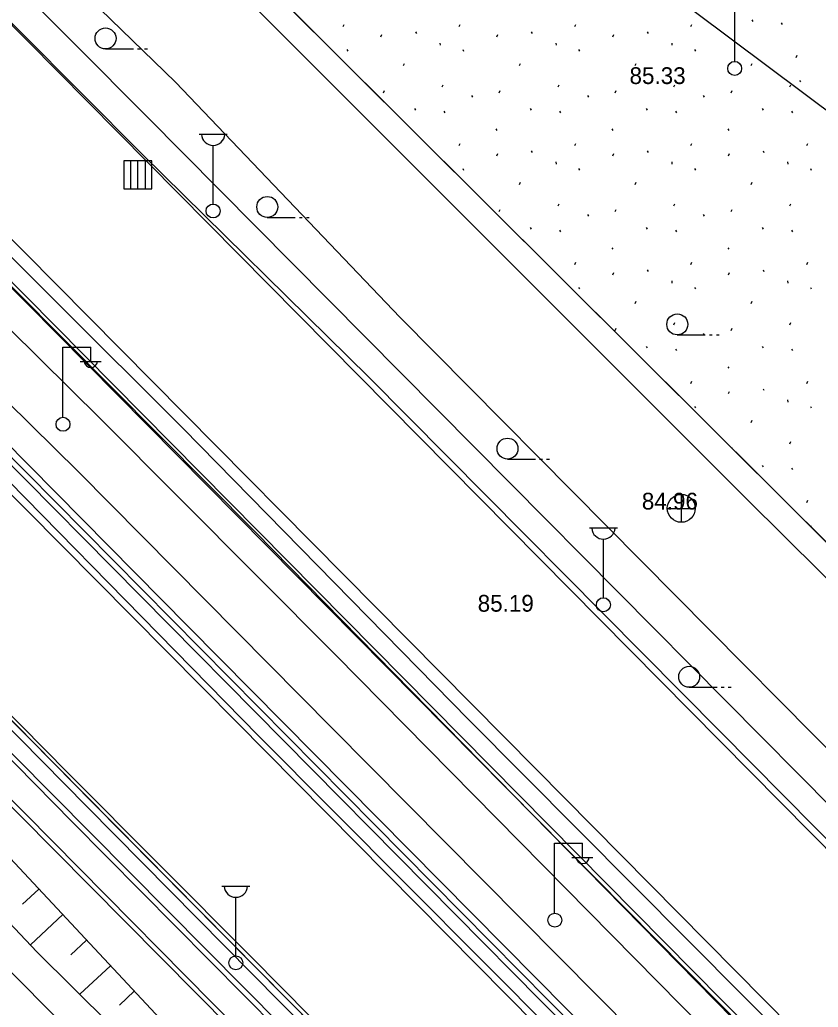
# Model space of a CAD drawing. Extents: x 412225 to 413380, y 4456471 to 4457189.
# Drawn here: x 412408.2 to 412465.4, y 4456938.5 to 4457009.2 of the extents above; entities that cross this region are included whole.
import ezdxf

# ---------------------------------------------------------------- set-up
doc = ezdxf.new("R2010")
doc.units = 0
for name, color, linetype in [('0_HALİHAZIR', 7, 'Continuous'), ('0_KADASTRO', 7, 'Continuous'), ('KALDIRIM', 7, 'Continuous'), ('Level 27', 7, 'Continuous'), ('Level 41', 7, 'Continuous'), ('Level 57', 7, 'Continuous'), ('Level 62', 7, 'Continuous'), ('Level 8', 7, 'Continuous')]:
    doc.layers.add(name, color=color, linetype=linetype)

msp = doc.modelspace()

# ---------------------------------------------------------------- linework, layer by layer
at = {"layer": '0_HALİHAZIR'}
for p, q in [((412459.38, 4457006.195), (412459.38, 4457010.388)), ((412414.357, 4457007.091), (412416.357, 4457007.091)), ((412416.657, 4457007.091), (412416.857, 4457007.091)), ((412417.157, 4457007.091), (412417.357, 4457007.091)), ((412421.055, 4457000.992), (412423.055, 4457000.992)), ((412422.055, 4456995.992), (412422.055, 4457000.185)), ((412417.675, 4456999.085), (412415.675, 4456999.085)), ((412415.675, 4456999.085), (412415.675, 4456997.085)), ((412417.675, 4456999.085), (412415.675, 4456999.085)), ((412415.675, 4456999.085), (412415.675, 4456997.085)), ((412416.18, 4456997.085), (412416.18, 4456999.085)), ((412416.675, 4456997.085), (412416.675, 4456999.085)), ((412417.223, 4456997.085), (412417.223, 4456999.085)), ((412417.675, 4456997.085), (412417.675, 4456999.085)), ((412417.675, 4456997.085), (412417.675, 4456999.085)), ((412415.675, 4456997.085), (412417.675, 4456997.085)), ((412415.675, 4456997.085), (412417.675, 4456997.085)), ((412425.932, 4456995.029), (412427.932, 4456995.029)), ((412428.232, 4456995.029), (412428.432, 4456995.029)), ((412428.732, 4456995.029), (412428.932, 4456995.029)), ((412455.275, 4456986.628), (412457.275, 4456986.628)), ((412457.575, 4456986.628), (412457.775, 4456986.628)), ((412458.075, 4456986.628), (412458.275, 4456986.628)), ((412411.305, 4456980.753), (412411.305, 4456985.753)), ((412411.305, 4456985.753), (412413.305, 4456985.753)), ((412413.305, 4456984.753), (412413.305, 4456985.753)), ((412412.545, 4456984.713), (412414.045, 4456984.713)), ((412443.122, 4456977.739), (412445.122, 4456977.739)), ((412445.422, 4456977.739), (412445.622, 4456977.739)), ((412445.922, 4456977.739), (412446.122, 4456977.739)), ((412455.572, 4456973.209), (412455.572, 4456975.209)), ((412454.552, 4456974.199), (412456.552, 4456974.199)), ((412448.984, 4456972.816), (412450.984, 4456972.816)), ((412449.984, 4456967.816), (412449.984, 4456972.009)), ((412456.122, 4456961.415), (412458.122, 4456961.415)), ((412458.422, 4456961.415), (412458.622, 4456961.415)), ((412458.922, 4456961.415), (412459.122, 4456961.415)), ((412446.497, 4456945.269), (412446.497, 4456950.269)), ((412446.497, 4456950.269), (412448.497, 4456950.269)), ((412448.497, 4456949.269), (412448.497, 4456950.269)), ((412447.737, 4456949.229), (412449.237, 4456949.229)), ((412422.685, 4456947.192), (412424.685, 4456947.192)), ((412409.586, 4456946.968), (412408.424, 4456945.882)), ((412423.685, 4456942.192), (412423.685, 4456946.385)), ((412411.293, 4456945.142), (412408.978, 4456942.978)), ((412413, 4456943.315), (412411.87, 4456942.259)), ((412414.707, 4456941.489), (412412.517, 4456939.441)), ((412416.414, 4456939.662), (412415.354, 4456938.671))]:
    msp.add_line(p, q, dxfattribs=at)
for points in [[(412301.706, 4457121.318), (412311.102, 4457113.16), (412330.158, 4457093.729), (412349.865, 4457074.031), (412372.694, 4457050.81), (412390.772, 4457032.428), (412419.372, 4457004.721)], [(412644.931, 4456753.555), (412630.555, 4456767.782), (412604.684, 4456793.709), (412582.154, 4456816.287), (412559.135, 4456839.628), (412534.75, 4456864.124), (412499.888, 4456899.345), (412487.433, 4456911.736), (412459.99, 4456939.333), (412440.337, 4456959.115), (412419.902, 4456979.921), (412392.691, 4457007.039), (412362.588, 4457037.58), (412334.209, 4457066.321), (412297.701, 4457103.437), (412284.18, 4457117.149)], [(412417.329, 4457002.236), (412381.395, 4457038.35), (412347.738, 4457072.166), (412303.554, 4457116.902)], [(412284.17, 4457116.265), (412296.803, 4457102.771), (412316.426, 4457082.291), (412338.061, 4457060.18), (412363.233, 4457034.899), (412383.867, 4457014.022), (412425.083, 4456972.499), (412446.131, 4456951.075), (412463.226, 4456933.647), (412501.75, 4456894.857), (412523.558, 4456872.918), (412554.446, 4456842.344)], [(412284.13, 4457112.788), (412289.83, 4457106.958), (412301.261, 4457094.649), (412314.468, 4457080.886), (412326.161, 4457068.858), (412338.147, 4457056.814), (412352.735, 4457042.191), (412364.851, 4457029.813), (412379.023, 4457015.687), (412394.281, 4457000.11), (412414.019, 4456980.608)], [(412284.053, 4457106.223), (412285.021, 4457105.263), (412297.191, 4457092.981), (412313.147, 4457076.941), (412329.843, 4457060.337), (412349.945, 4457039.93), (412369.246, 4457020.5), (412382.389, 4457007.084), (412402.176, 4456986.924), (412412.412, 4456976.824)], [(412283.977, 4457099.685), (412295.712, 4457088.125), (412305.906, 4457077.537), (412321.323, 4457062.165), (412336.439, 4457046.989), (412355.577, 4457027.567), (412370.703, 4457012.276), (412385.426, 4456997.416), (412408.728, 4456974.086)], [(412283.985, 4457100.322), (412303.353, 4457080.961), (412332.911, 4457051.149), (412362.488, 4457021.336), (412400.253, 4456983.455), (412425.306, 4456957.949), (412451.956, 4456931.175), (412483.613, 4456899.459), (412507.045, 4456875.463), (412533.953, 4456848.693), (412570.746, 4456810.938), (412594.382, 4456786.967), (412618.72, 4456762.275), (412633.267, 4456747.178), (412636.335, 4456744.215)], [(412340.966, 4457076.102), (412361.717, 4457055.451), (412377.534, 4457039.414), (412399.513, 4457017.111), (412417.007, 4456999.535), (412433.199, 4456983.611)], [(412361.686, 4456992.138), (412361.531, 4456995.933), (412361.158, 4456998.952), (412360.693, 4457001.526), (412360.272, 4457003.327), (412359.32, 4457005.483), (412358.676, 4457006.822), (412358.336, 4457007.638), (412358.163, 4457008.228), (412358.124, 4457008.638), (412358.202, 4457008.918), (412358.315, 4457009.019), (412358.874, 4457008.994), (412365.521, 4457001.843), (412376.984, 4456990.177), (412386.707, 4456980.556), (412399.955, 4456967.14), (412411.666, 4456955.297), (412424.812, 4456942.094), (412439.594, 4456927.156)], [(412513.116, 4456909.938), (412497.081, 4456925.639), (412469.945, 4456953.037), (412435.441, 4456987.862), (412419.372, 4457004.721)], [(412359.87, 4457004.239), (412376.982, 4456987.314), (412402.386, 4456961.963), (412429.729, 4456934.421), (412459.529, 4456904.105), (412465.296, 4456898.03)], [(412417.321, 4457002.244), (412443.331, 4456975.989), (412466.46, 4456952.659), (412490.035, 4456928.962), (412506.529, 4456912.027), (412510.582, 4456907.986)], [(412364.261, 4456996.871), (412370.245, 4456990.594), (412389.047, 4456971.622), (412405.68, 4456954.805), (412425.867, 4456934.44)], [(412645.421, 4456754.062), (412629.127, 4456770.178), (412599.147, 4456800.409), (412567.615, 4456832.31), (412536.489, 4456863.396), (412502.72, 4456897.599), (412471.675, 4456928.735), (412445.148, 4456955.565), (412406.259, 4456994.837)], [(412637.165, 4456746.318), (412618.159, 4456765.78), (412589.798, 4456794.375), (412560.702, 4456823.748), (412525.834, 4456858.92), (412495.532, 4456889.87), (412469.975, 4456915.531), (412420.275, 4456965.756), (412393.731, 4456992.619)], [(412446.303, 4456903.127), (412444.442, 4456907.882), (412437.794, 4456916.266), (412419.952, 4456935.877), (412400.449, 4456956.745), (412375.57, 4456982.136), (412370.301, 4456987.22), (412368.113, 4456988.47), (412366.809, 4456988.895), (412364.507, 4456988.91)], [(412364.559, 4456988.91), (412369.327, 4456983.178), (412377.302, 4456975.126), (412390.738, 4456962.288), (412409.437, 4456942.493), (412422.613, 4456929.438), (412434.169, 4456915.9), (412443.007, 4456906.151), (412446.303, 4456903.127)], [(412433.199, 4456983.611), (412458.357, 4456958.224), (412478.594, 4456937.778), (412494.707, 4456921.709), (412506.6, 4456909.868), (412508.244, 4456908.725), (412509.715, 4456908.155), (412510.968, 4456907.91), (412512.709, 4456907.952), (412514.827, 4456908.164), (412517.02, 4456908.788), (412521.642, 4456910.812), (412528.714, 4456914.991), (412542.04, 4456923.109), (412563.128, 4456935.466), (412569.855, 4456939.641), (412584.556, 4456948.006), (412584.762, 4456948.165)], [(412414.019, 4456980.608), (412430.818, 4456963.728), (412462.102, 4456931.987), (412481.52, 4456912.466), (412499.923, 4456893.817), (412530.253, 4456863.229), (412548.59, 4456844.546), (412567.492, 4456825.478), (412597.357, 4456795.212), (412619.629, 4456772.724)], [(412412.412, 4456976.824), (412430.58, 4456958.484), (412471.136, 4456917.576), (412494.611, 4456893.791), (412529.094, 4456859.09), (412552.718, 4456835.192), (412591.392, 4456796.015), (412615.481, 4456771.779), (412632.916, 4456754.119)], [(412635.095, 4456744.706), (412621.293, 4456758.968), (412594.514, 4456786.189), (412564.28, 4456816.959), (412527.989, 4456853.886), (412497.963, 4456883.985), (412468.818, 4456913.357), (412423.738, 4456958.933), (412408.728, 4456974.086)]]:
    msp.add_lwpolyline(points, dxfattribs=at)
for centre, radius in [((412414.357, 4457007.841), 0.75), ((412459.38, 4457005.695), 0.5), ((412425.932, 4456995.779), 0.75), ((412422.055, 4456995.492), 0.5), ((412455.275, 4456987.378), 0.75), ((412411.315, 4456980.229), 0.5), ((412443.122, 4456978.489), 0.75), ((412455.557, 4456974.217), 1), ((412449.984, 4456967.316), 0.5), ((412456.122, 4456962.165), 0.75), ((412446.507, 4456944.745), 0.5), ((412423.685, 4456941.692), 0.5)]:
    msp.add_circle(centre, radius, dxfattribs=at)
for centre, radius, start, end in [((412422.055, 4457001.022), 0.837, 183.298, 356.90719), ((412413.305, 4456984.757), 0.474, 184.83843, 355.14641), ((412449.984, 4456972.846), 0.837, 183.298, 356.90719), ((412448.497, 4456949.273), 0.474, 184.83843, 355.14641), ((412423.685, 4456947.221), 0.837, 183.298, 356.90719)]:
    msp.add_arc(centre, radius, start, end, dxfattribs=at)
at = {"layer": '0_KADASTRO'}
for points in [[(412531.386, 4456906.626), (412255.662, 4457181.172)], [(412245.621, 4457084.985), (412262.788, 4457087.767), (412498.109, 4456849.333), (412486.377, 4456828.685), (412245.456, 4457070.818)]]:
    msp.add_lwpolyline(points, dxfattribs=at)
at = {"layer": 'KALDIRIM'}
for p, q in [((412272.318, 4457095.296), (412413.048, 4456952.849)), ((412271.251, 4457094.241), (412411.981, 4456951.795)), ((412269.828, 4457092.836), (412410.559, 4456950.389)), ((412413.048, 4456952.849), (412435.059, 4456930.599)), ((412413.404, 4456953.201), (412435.415, 4456930.951)), ((412411.981, 4456951.795), (412433.993, 4456929.544)), ((412410.559, 4456950.389), (412432.571, 4456928.138))]:
    msp.add_line(p, q, dxfattribs=at)
at = {"layer": 'Level 27'}
msp.add_line((412531.386, 4456906.626), (412255.662, 4457181.172), dxfattribs=at)
at = {"layer": 'Level 41'}
for p, q in [((412431.364, 4457008.684), (412431.435, 4457008.843)), ((412439.657, 4457008.684), (412439.728, 4457008.843)), ((412447.95, 4457008.684), (412448.021, 4457008.843)), ((412456.243, 4457008.684), (412456.314, 4457008.843)), ((412460.616, 4457009.161), (412460.686, 4457009.054)), ((412462.713, 4457008.948), (412462.783, 4457008.84)), ((412434.063, 4457007.955), (412434.135, 4457008.115)), ((412436.528, 4457008.3), (412436.599, 4457008.193)), ((412442.356, 4457007.955), (412442.428, 4457008.115)), ((412444.821, 4457008.3), (412444.892, 4457008.193)), ((412450.649, 4457007.955), (412450.721, 4457008.115)), ((412453.114, 4457008.3), (412453.185, 4457008.193)), ((412438.286, 4457007.509), (412438.304, 4457007.349)), ((412446.579, 4457007.509), (412446.597, 4457007.349)), ((412454.872, 4457007.509), (412454.89, 4457007.349)), ((412431.623, 4457007.039), (412431.693, 4457006.932)), ((412439.916, 4457007.039), (412439.986, 4457006.932)), ((412448.209, 4457007.039), (412448.279, 4457006.932)), ((412456.502, 4457007.039), (412456.572, 4457006.932)), ((412463.785, 4457006.483), (412463.857, 4457006.641)), ((412435.679, 4457005.895), (412435.751, 4457006.055)), ((412443.972, 4457005.895), (412444.044, 4457006.055)), ((412452.265, 4457005.895), (412452.337, 4457006.055)), ((412460.558, 4457005.895), (412460.63, 4457006.055)), ((412438.451, 4457004.365), (412438.521, 4457004.525)), ((412446.744, 4457004.365), (412446.814, 4457004.525)), ((412455.037, 4457004.365), (412455.107, 4457004.525)), ((412463.33, 4457004.365), (412463.4, 4457004.525)), ((412464.027, 4457004.835), (412464.096, 4457004.728)), ((412434.241, 4457003.957), (412434.312, 4457004.117)), ((412440.546, 4457003.749), (412440.617, 4457003.643)), ((412442.534, 4457003.957), (412442.605, 4457004.117)), ((412448.839, 4457003.749), (412448.91, 4457003.643)), ((412450.827, 4457003.957), (412450.898, 4457004.117)), ((412457.132, 4457003.749), (412457.203, 4457003.643)), ((412459.12, 4457003.957), (412459.191, 4457004.117)), ((412436.461, 4457002.82), (412436.532, 4457002.713)), ((412438.56, 4457002.628), (412438.631, 4457002.521)), ((412444.754, 4457002.82), (412444.825, 4457002.713)), ((412446.853, 4457002.628), (412446.924, 4457002.521)), ((412453.047, 4457002.82), (412453.118, 4457002.713)), ((412455.146, 4457002.628), (412455.217, 4457002.521)), ((412461.34, 4457002.82), (412461.411, 4457002.713)), ((412463.439, 4457002.628), (412463.51, 4457002.521)), ((412442.298, 4457001.367), (412442.369, 4457001.26)), ((412450.591, 4457001.367), (412450.662, 4457001.26)), ((412458.884, 4457001.367), (412458.955, 4457001.26)), ((412439.657, 4457000.174), (412439.728, 4457000.333)), ((412447.95, 4457000.174), (412448.021, 4457000.333)), ((412456.243, 4457000.174), (412456.314, 4457000.333)), ((412464.536, 4457000.174), (412464.607, 4457000.333)), ((412442.356, 4456999.445), (412442.428, 4456999.605)), ((412444.821, 4456999.79), (412444.892, 4456999.683)), ((412450.649, 4456999.445), (412450.721, 4456999.605)), ((412453.114, 4456999.79), (412453.185, 4456999.683)), ((412458.942, 4456999.445), (412459.014, 4456999.605)), ((412461.407, 4456999.79), (412461.478, 4456999.683)), ((412446.579, 4456998.999), (412446.597, 4456998.839)), ((412454.872, 4456998.999), (412454.89, 4456998.839)), ((412463.165, 4456998.999), (412463.183, 4456998.839)), ((412439.916, 4456998.529), (412439.986, 4456998.422)), ((412448.209, 4456998.529), (412448.279, 4456998.422)), ((412456.502, 4456998.529), (412456.572, 4456998.422)), ((412464.795, 4456998.529), (412464.865, 4456998.422)), ((412443.972, 4456997.385), (412444.044, 4456997.545)), ((412452.265, 4456997.385), (412452.337, 4456997.545)), ((412460.558, 4456997.385), (412460.63, 4456997.545)), ((412446.744, 4456995.855), (412446.814, 4456996.015)), ((412455.037, 4456995.855), (412455.107, 4456996.015)), ((412463.33, 4456995.855), (412463.4, 4456996.015)), ((412442.534, 4456995.447), (412442.605, 4456995.607)), ((412448.839, 4456995.239), (412448.91, 4456995.133)), ((412450.827, 4456995.447), (412450.898, 4456995.607)), ((412457.132, 4456995.239), (412457.203, 4456995.133)), ((412459.12, 4456995.447), (412459.191, 4456995.607)), ((412444.754, 4456994.31), (412444.825, 4456994.203)), ((412446.853, 4456994.118), (412446.924, 4456994.011)), ((412453.047, 4456994.31), (412453.118, 4456994.203)), ((412455.146, 4456994.118), (412455.217, 4456994.011)), ((412461.34, 4456994.31), (412461.411, 4456994.203)), ((412463.439, 4456994.118), (412463.51, 4456994.011)), ((412450.591, 4456992.857), (412450.662, 4456992.75)), ((412458.884, 4456992.857), (412458.955, 4456992.75)), ((412447.95, 4456991.664), (412448.021, 4456991.823)), ((412456.243, 4456991.664), (412456.314, 4456991.823)), ((412464.536, 4456991.664), (412464.607, 4456991.823)), ((412450.649, 4456990.935), (412450.721, 4456991.095)), ((412453.114, 4456991.28), (412453.185, 4456991.173)), ((412458.942, 4456990.935), (412459.014, 4456991.095)), ((412461.407, 4456991.28), (412461.478, 4456991.173)), ((412454.872, 4456990.489), (412454.89, 4456990.329)), ((412463.165, 4456990.489), (412463.183, 4456990.329)), ((412448.209, 4456990.019), (412448.279, 4456989.912)), ((412456.502, 4456990.019), (412456.572, 4456989.912)), ((412464.795, 4456990.019), (412464.865, 4456989.912)), ((412452.265, 4456988.875), (412452.337, 4456989.035)), ((412460.558, 4456988.875), (412460.63, 4456989.035)), ((412455.037, 4456987.345), (412455.107, 4456987.505)), ((412463.33, 4456987.345), (412463.4, 4456987.505)), ((412450.827, 4456986.937), (412450.898, 4456987.097)), ((412457.132, 4456986.729), (412457.203, 4456986.623)), ((412459.12, 4456986.937), (412459.191, 4456987.097)), ((412453.047, 4456985.8), (412453.118, 4456985.693)), ((412455.146, 4456985.608), (412455.217, 4456985.501)), ((412461.34, 4456985.8), (412461.411, 4456985.693)), ((412463.439, 4456985.608), (412463.51, 4456985.501)), ((412458.884, 4456984.347), (412458.955, 4456984.24)), ((412456.243, 4456983.154), (412456.314, 4456983.313)), ((412464.536, 4456983.154), (412464.607, 4456983.313)), ((412458.942, 4456982.425), (412459.014, 4456982.585)), ((412461.407, 4456982.77), (412461.478, 4456982.663)), ((412463.165, 4456981.979), (412463.183, 4456981.819)), ((412456.502, 4456981.509), (412456.572, 4456981.402)), ((412464.795, 4456981.509), (412464.865, 4456981.402)), ((412460.558, 4456980.365), (412460.63, 4456980.525)), ((412463.33, 4456978.835), (412463.4, 4456978.995)), ((412459.168, 4456978.535), (412459.191, 4456978.587)), ((412461.34, 4456977.29), (412461.411, 4456977.183)), ((412463.439, 4456977.098), (412463.51, 4456976.991)), ((412464.536, 4456974.644), (412464.607, 4456974.803)), ((412464.795, 4456972.999), (412464.865, 4456972.892))]:
    msp.add_line(p, q, dxfattribs=at)
at = {"layer": 'Level 57'}
msp.add_line((412456.481, 4457009.795), (412501.285, 4456976.281), dxfattribs=at)
at = {"layer": 'Level 62'}
for p, q in [((412283.77, 4457102.474), (412490.887, 4456893.113)), ((412284.055, 4457102.756), (412491.172, 4456893.395)), ((412272.673, 4457095.647), (412413.404, 4456953.201)), ((412326.793, 4457071.711), (412497.295, 4456899.362)), ((412327.007, 4457071.922), (412497.51, 4456899.572)), ((412393.43, 4457023.16), (412517.28, 4456897.96)), ((412400.48, 4456966.264), (412503.388, 4456862.241))]:
    msp.add_line(p, q, dxfattribs=at)
for points in [[(412284.13, 4457112.788), (412289.83, 4457106.958), (412301.261, 4457094.649), (412314.468, 4457080.886), (412326.161, 4457068.858), (412338.147, 4457056.814), (412352.735, 4457042.191), (412364.851, 4457029.813), (412379.023, 4457015.687), (412394.281, 4457000.11), (412414.019, 4456980.608)], [(412284.053, 4457106.223), (412285.021, 4457105.263), (412297.191, 4457092.981), (412313.147, 4457076.941), (412329.843, 4457060.337), (412349.945, 4457039.93), (412369.246, 4457020.5), (412382.389, 4457007.084), (412402.176, 4456986.924), (412412.412, 4456976.824)], [(412414.019, 4456980.608), (412430.818, 4456963.728), (412462.102, 4456931.987), (412481.52, 4456912.466), (412499.923, 4456893.817), (412530.253, 4456863.229), (412548.59, 4456844.546), (412567.492, 4456825.478), (412597.357, 4456795.212), (412619.629, 4456772.724)], [(412412.412, 4456976.824), (412430.58, 4456958.484), (412471.136, 4456917.576), (412494.611, 4456893.791), (412529.094, 4456859.09), (412552.718, 4456835.192), (412591.392, 4456796.015), (412615.481, 4456771.779), (412632.916, 4456754.119)]]:
    msp.add_lwpolyline(points, dxfattribs=at)
at = {"layer": 'Level 8'}
msp.add_lwpolyline([(412706.1, 4457175.965), (412751.217, 4457041.463), (412764.575, 4457001.385), (412790.361, 4457003.87), (412821.118, 4456953.851), (412699.954, 4456860.338), (412631.485, 4456804.219), (412585.777, 4456849.927), (412523.439, 4456912.266), (412460.309, 4456974.831), (412403.512, 4457031.625), (412342.192, 4457092.946), (412287.774, 4457146.913), (412253.259, 4457181.199)], dxfattribs=at)

# ---------------------------------------------------------------- texts
at = {"layer": '0_HALİHAZIR'}
for s, p in [('85.33', (412451.855, 4457004.577)), ('84.96', (412452.735, 4456974.13)), ('85.19', (412440.99, 4456966.821))]:
    msp.add_text(s, height=1.2, dxfattribs=at).set_placement(p)

doc.saveas('drawing.dxf')
